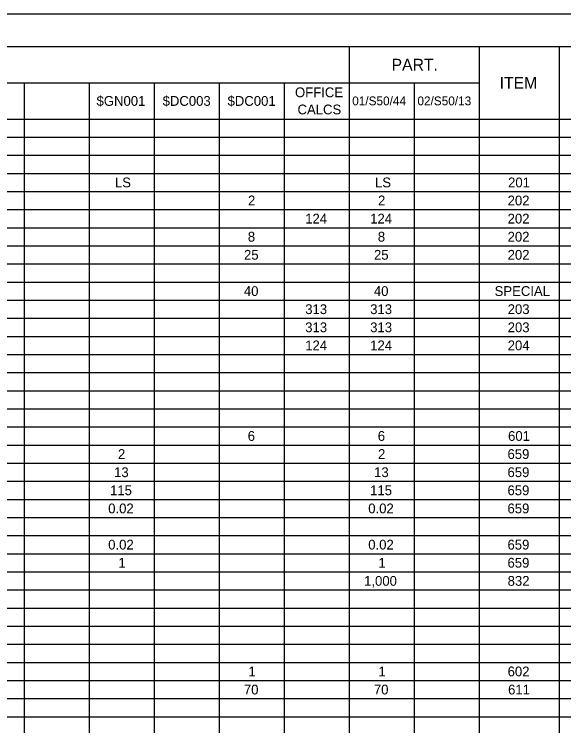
# Model space of a CAD drawing. Extents: x 0 to 34, y 0 to 22.
# Drawn here: x 8.38 to 16.87, y 11 to 22 of the extents above; entities that cross this region are included whole.
import ezdxf

# ---------------------------------------------------------------- set-up
doc = ezdxf.new("R2010")
doc.units = 0
for name, color, linetype in [('SH_Border', 7, 'Continuous'), ('SH_Cut_Line', 7, 'Continuous'), ('SH_Text', 7, 'Continuous')]:
    doc.layers.add(name, color=color, linetype=linetype)

msp = doc.modelspace()

# ---------------------------------------------------------------- linework, layer by layer
at = {"layer": 'SH_Border'}
msp.add_lwpolyline([(1.5, 21.5), (33.5, 21.5), (33.5, 0.5), (1.5, 0.5)], close=True, dxfattribs=at)
at = {"layer": 'SH_Cut_Line'}
msp.add_lwpolyline([(0, 0), (34, 0), (34, 22), (0, 22)], close=True, dxfattribs=at)
at = {"layer": 'SH_Text'}
for p, q in [((1.5, 21.5), (32, 21.5)), ((13.555, 21.5), (13.555, 0.502)), ((15.564, 21.5), (15.564, 0.502)), ((16.799, 21.5), (16.799, 0.502)), ((1.5, 20.94), (15.564, 20.94)), ((8.532, 20.94), (8.532, 0.502)), ((9.537, 20.94), (9.537, 0.502)), ((10.541, 20.94), (10.541, 0.502)), ((11.546, 20.94), (11.546, 0.502)), ((12.55, 20.94), (12.55, 0.502)), ((14.56, 20.94), (14.56, 0.502)), ((1.5, 20.38), (32, 20.38)), ((1.5, 20.1), (32, 20.1)), ((1.5, 19.82), (32, 19.82)), ((1.5, 19.54), (32, 19.54)), ((1.5, 19.26), (32, 19.26)), ((1.5, 18.98), (32, 18.98)), ((1.5, 18.7), (32, 18.7)), ((1.5, 18.42), (32, 18.42)), ((1.5, 18.14), (32, 18.14)), ((1.5, 17.86), (32, 17.86)), ((1.5, 17.58), (32, 17.58)), ((1.5, 17.3), (32, 17.3)), ((1.5, 17.021), (32, 17.021)), ((1.5, 16.741), (32, 16.741)), ((1.5, 16.461), (32, 16.461)), ((1.5, 16.181), (32, 16.181)), ((1.5, 15.901), (32, 15.901)), ((1.5, 15.621), (32, 15.621)), ((1.5, 15.341), (32, 15.341)), ((1.5, 15.061), (32, 15.061)), ((1.5, 14.781), (32, 14.781)), ((1.5, 14.501), (32, 14.501)), ((1.5, 14.221), (32, 14.221)), ((1.5, 13.941), (32, 13.941)), ((1.5, 13.661), (32, 13.661)), ((1.5, 13.381), (32, 13.381)), ((1.5, 13.101), (32, 13.101)), ((1.5, 12.821), (32, 12.821)), ((1.5, 12.541), (32, 12.541)), ((1.5, 12.261), (32, 12.261)), ((1.5, 11.981), (32, 11.981)), ((1.5, 11.701), (32, 11.701)), ((1.5, 11.421), (32, 11.421)), ((1.5, 11.141), (32, 11.141))]:
    msp.add_line(p, q, dxfattribs=at)

# ---------------------------------------------------------------- texts
for s, height, p in [('PART.', 0.1818, (14.211, 21.129)), ('ITEM', 0.1818, (15.88, 20.849)), ('OFFICE ', 0.1515, (12.718, 20.717)), ('$GN001', 0.1515, (9.651, 20.584)), ('$DC003', 0.1515, (10.672, 20.584)), ('$DC001', 0.1515, (11.676, 20.584)), ('01/S50/44', 0.1364, (13.602, 20.592)), ('02/S50/13', 0.1364, (14.61, 20.592)), ('CALCS', 0.1515, (12.757, 20.452)), ('LS', 0.1515, (9.935, 19.324)), ('LS', 0.1515, (13.954, 19.324)), ('201', 0.1515, (16.011, 19.324)), ('2', 0.152, (11.992, 19.045)), ('2', 0.152, (14.001, 19.045)), ('202', 0.1515, (16.004, 19.045)), ('124', 0.1515, (12.876, 18.765)), ('124', 0.1515, (13.88, 18.765)), ('202', 0.1515, (16.004, 18.765)), ('8', 0.152, (11.989, 18.485)), ('8', 0.152, (13.998, 18.485)), ('202', 0.1515, (16.004, 18.485)), ('25', 0.1515, (11.93, 18.205)), ('25', 0.1515, (13.939, 18.205)), ('202', 0.1515, (16.004, 18.205)), ('40', 0.1515, (11.928, 17.645)), ('40', 0.1515, (13.937, 17.645)), ('SPECIAL', 0.1515, (15.803, 17.645)), ('313', 0.1515, (12.876, 17.365)), ('313', 0.1515, (13.88, 17.365)), ('203', 0.1515, (16.005, 17.365)), ('313', 0.1515, (12.876, 17.085)), ('313', 0.1515, (13.88, 17.085)), ('203', 0.1515, (16.005, 17.085)), ('124', 0.1515, (12.876, 16.805)), ('124', 0.1515, (13.88, 16.805)), ('204', 0.1515, (16.005, 16.805)), ('6', 0.152, (11.987, 15.405)), ('6', 0.152, (13.997, 15.405)), ('601', 0.1515, (16.011, 15.405)), ('2', 0.152, (9.982, 15.125)), ('2', 0.152, (14.001, 15.125)), ('659', 0.1515, (16.002, 15.125)), ('13', 0.1515, (9.922, 14.845)), ('13', 0.1515, (13.941, 14.845)), ('659', 0.1515, (16.002, 14.845)), ('115', 0.1515, (9.86, 14.565)), ('115', 0.1515, (13.879, 14.565)), ('659', 0.1515, (16.002, 14.565)), ('0.02', 0.1515, (9.831, 14.285)), ('0.02', 0.1515, (13.85, 14.285)), ('659', 0.1515, (16.002, 14.285)), ('0.02', 0.1515, (9.831, 13.725)), ('0.02', 0.1515, (13.85, 13.725)), ('659', 0.1515, (16.002, 13.725)), ('1', 0.152, (9.989, 13.445)), ('1', 0.152, (14.008, 13.445)), ('659', 0.1515, (16.002, 13.445)), ('1,000', 0.1515, (13.786, 13.165)), ('832', 0.1515, (16.004, 13.165)), ('1', 0.152, (11.999, 11.765)), ('1', 0.152, (14.008, 11.765)), ('602', 0.1515, (16.004, 11.765)), ('70', 0.1515, (11.928, 11.485)), ('70', 0.1515, (13.937, 11.485)), ('611', 0.1515, (16.011, 11.485))]:
    msp.add_text(s, height=height, dxfattribs=at).set_placement(p)

doc.saveas('drawing.dxf')
